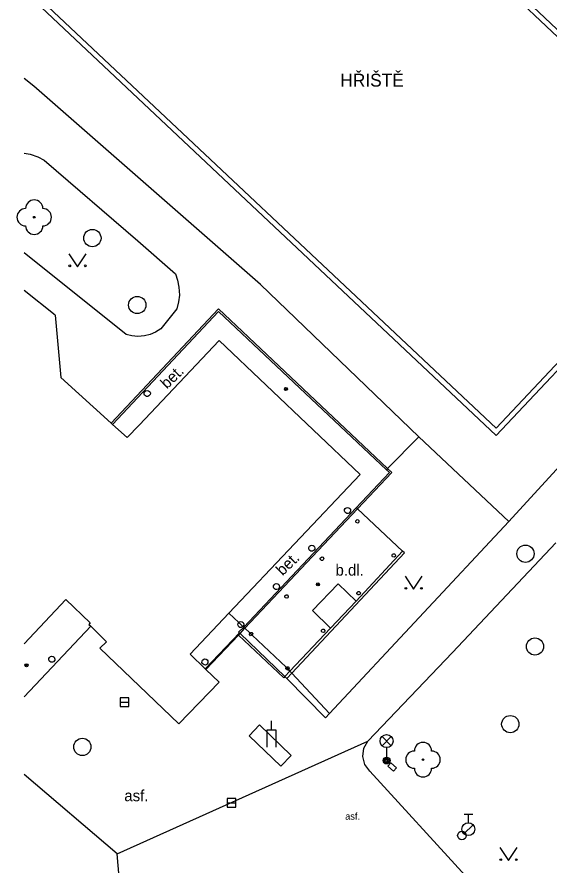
# Model space of a CAD drawing. Extents: x -598932 to -598196, y -1162207 to -1161504.
# Drawn here: x -598932.43 to -598901.6, y -1161841.73 to -1161792.56 of the extents above; entities that cross this region are included whole.
import ezdxf

# ---------------------------------------------------------------- set-up
doc = ezdxf.new("R2010")
doc.units = 0
for name, color, linetype in [('Level 22', 7, 'Continuous'), ('Level 27', 7, 'Continuous'), ('Level 28', 7, 'Continuous'), ('Level 33', 7, 'Continuous'), ('Level 36', 7, 'Continuous'), ('Level 38', 7, 'Continuous'), ('Level 39', 7, 'Continuous'), ('silnoproud - povrch.  znaky a  RIS  skut. velikost', 7, 'Continuous'), ('specificka linie pasportu komunikaci', 7, 'Continuous'), ('TM - budovy zdene_ betonove - NP', 7, 'Continuous'), ('TM - budovy zdene_ betonove - VP', 7, 'Continuous'), ('TM - chodniky - VP', 7, 'Continuous'), ('TM - plot dreveny_ kovovy - VP', 7, 'Continuous'), ('TM - pomocna konstrukcna linie', 7, 'Continuous'), ('TM - popis objektu', 7, 'Continuous'), ('TM - popis povrchu', 7, 'Continuous'), ('TM - rozhrani ploch obecne - NP', 7, 'Continuous'), ('TM - rozhrani ploch obecne - VP', 7, 'Continuous'), ('TM - vjezd na pozemek', 7, 'Continuous')]:
    doc.layers.add(name, color=color, linetype=linetype)

msp = doc.modelspace()

# ---------------------------------------------------------------- linework, layer by layer
at = {"layer": 'Level 22'}
for centre in [(-598931.43, -1161804.17), (-598908.9, -1161835.62)]:
    msp.add_circle(centre, 0.05, dxfattribs=at)
for centre, start, end in [((-598931.43, -1161803.67), 0, 180), ((-598931.93, -1161804.17), 90, 270), ((-598930.93, -1161804.17), 270, 90), ((-598931.43, -1161804.67), 180, 0), ((-598908.9, -1161835.12), 0, 180), ((-598909.4, -1161835.62), 90, 270), ((-598908.4, -1161835.62), 270, 90), ((-598908.9, -1161836.12), 180, 0)]:
    msp.add_arc(centre, 0.5, start, end, dxfattribs=at)
at = {"layer": 'Level 27'}
for p, q in [((-598926.44, -1161832.29), (-598925.94, -1161832.29)), ((-598920.24, -1161838.12), (-598919.74, -1161838.12))]:
    msp.add_line(p, q, dxfattribs=at)
for points in [[(-598926.44, -1161832.54), (-598925.94, -1161832.54), (-598925.94, -1161832.04), (-598926.44, -1161832.04)], [(-598920.24, -1161838.37), (-598919.74, -1161838.37), (-598919.74, -1161837.87), (-598920.24, -1161837.87)]]:
    msp.add_lwpolyline(points, close=True, dxfattribs=at)
for centre in [(-598928.06, -1161805.38), (-598925.46, -1161809.26), (-598902.96, -1161823.68), (-598902.41, -1161829.06), (-598903.84, -1161833.56), (-598928.64, -1161834.88)]:
    msp.add_circle(centre, 0.5, dxfattribs=at)
at = {"layer": 'Level 28'}
for p, q in [((-598906.52, -1161838.775), (-598906.02, -1161838.775)), ((-598906.27, -1161839.275), (-598906.27, -1161838.775)), ((-598906.528, -1161839.922), (-598905.998, -1161839.392))]:
    msp.add_line(p, q, dxfattribs=at)
for centre, radius in [((-598906.27, -1161839.65), 0.375), ((-598906.64, -1161840.02), 0.25)]:
    msp.add_circle(centre, radius, dxfattribs=at)
at = {"layer": 'Level 33'}
for p, q in [((-598911.275, -1161834.81), (-598910.745, -1161834.28)), ((-598911.275, -1161834.28), (-598910.745, -1161834.81)), ((-598911.01, -1161834.92), (-598911.01, -1161835.67))]:
    msp.add_line(p, q, dxfattribs=at)
for centre, radius in [((-598911.01, -1161834.545), 0.375), ((-598911.01, -1161835.67), 0.2), ((-598911.01, -1161835.67), 0.145), ((-598911.01, -1161835.67), 0.0876)]:
    msp.add_circle(centre, radius, dxfattribs=at)
at = {"layer": 'Level 36'}
for points in [[(-598929.42, -1161806.29), (-598928.92, -1161807.04), (-598928.42, -1161806.29)], [(-598909.94, -1161824.99), (-598909.44, -1161825.74), (-598908.94, -1161824.99)], [(-598904.44, -1161840.72), (-598903.94, -1161841.47), (-598903.44, -1161840.72)]]:
    msp.add_lwpolyline(points, dxfattribs=at)
for centre in [(-598929.37, -1161806.99), (-598928.471, -1161806.99), (-598909.89, -1161825.69), (-598908.991, -1161825.69), (-598904.39, -1161841.42), (-598903.491, -1161841.42)]:
    msp.add_circle(centre, 0.05, dxfattribs=at)
at = {"layer": 'Level 38'}
msp.add_line((-598917.68, -1161833.9), (-598917.68, -1161833.37), dxfattribs=at)
msp.add_lwpolyline([(-598917.93, -1161834.9), (-598917.93, -1161833.9), (-598917.43, -1161833.9), (-598917.43, -1161834.9)], dxfattribs=at)
at = {"layer": 'Level 39'}
for centre, radius in [((-598916.84, -1161814.13), 0.09), ((-598916.84, -1161814.13), 0.0398), ((-598914.99, -1161825.46), 0.09), ((-598914.99, -1161825.46), 0.0398), ((-598931.88, -1161830.15), 0.09), ((-598931.88, -1161830.15), 0.0398)]:
    msp.add_circle(centre, radius, dxfattribs=at)
at = {"layer": 'silnoproud - povrch.  znaky a  RIS  skut. velikost'}
for points in [[(-598910.76, -1161835.81), (-598910.93, -1161836)], [(-598910.93, -1161836), (-598910.61, -1161836.29)], [(-598910.44, -1161836.1), (-598910.76, -1161835.81)], [(-598910.61, -1161836.29), (-598910.44, -1161836.1)]]:
    msp.add_lwpolyline(points, dxfattribs=at)
at = {"layer": 'specificka linie pasportu komunikaci'}
msp.add_lwpolyline([(-598926.62, -1161841.08), (-598912.1, -1161834.54)], dxfattribs=at)
at = {"layer": 'TM - budovy zdene_ betonove - NP'}
for points in [[(-598925.35, -1161816.22), (-598920.71, -1161811.31)], [(-598920.71, -1161811.31), (-598912.55, -1161819.08)], [(-598925.05, -1161814.34), (-598925.01, -1161814.28)], [(-598925.05, -1161814.42), (-598925.05, -1161814.34)], [(-598925.01, -1161814.28), (-598924.96, -1161814.23)], [(-598924.96, -1161814.23), (-598924.89, -1161814.21)], [(-598924.89, -1161814.21), (-598924.81, -1161814.23)], [(-598924.81, -1161814.23), (-598924.75, -1161814.27)], [(-598924.75, -1161814.27), (-598924.72, -1161814.32)], [(-598924.72, -1161814.32), (-598924.7, -1161814.38)], [(-598924.7, -1161814.38), (-598924.71, -1161814.44)], [(-598925.03, -1161814.48), (-598925.05, -1161814.42)], [(-598924.99, -1161814.52), (-598925.03, -1161814.48)], [(-598924.93, -1161814.56), (-598924.99, -1161814.52)], [(-598924.85, -1161814.56), (-598924.93, -1161814.56)], [(-598924.78, -1161814.53), (-598924.85, -1161814.56)], [(-598924.71, -1161814.44), (-598924.78, -1161814.53)], [(-598926.97, -1161816.11), (-598926.9, -1161816.18)], [(-598926.9, -1161816.18), (-598926.04, -1161816.95)], [(-598926.04, -1161816.95), (-598925.35, -1161816.22)], [(-598912.55, -1161819.08), (-598920.15, -1161827.12)], [(-598919.22, -1161828), (-598912.69, -1161821.07)], [(-598913.44, -1161821.12), (-598913.41, -1161821.06)], [(-598913.44, -1161821.2), (-598913.44, -1161821.12)], [(-598913.42, -1161821.26), (-598913.44, -1161821.2)], [(-598913.38, -1161821.3), (-598913.42, -1161821.26)], [(-598913.41, -1161821.06), (-598913.35, -1161821.01)], [(-598913.35, -1161821.01), (-598913.28, -1161821)], [(-598913.28, -1161821), (-598913.2, -1161821.01)], [(-598913.2, -1161821.01), (-598913.14, -1161821.05)], [(-598913.14, -1161821.05), (-598913.11, -1161821.1)], [(-598913.1, -1161821.22), (-598913.14, -1161821.28)], [(-598913.11, -1161821.1), (-598913.1, -1161821.16)], [(-598913.1, -1161821.16), (-598913.1, -1161821.22)], [(-598913.32, -1161821.34), (-598913.38, -1161821.3)], [(-598913.24, -1161821.35), (-598913.32, -1161821.34)], [(-598913.17, -1161821.32), (-598913.24, -1161821.35)], [(-598913.14, -1161821.28), (-598913.17, -1161821.32)], [(-598912.8, -1161821.77), (-598912.76, -1161821.73)], [(-598912.76, -1161821.73), (-598912.72, -1161821.7)], [(-598912.72, -1161821.7), (-598912.66, -1161821.71)], [(-598912.66, -1161821.71), (-598912.61, -1161821.761)], [(-598912.8, -1161821.83), (-598912.8, -1161821.77)], [(-598912.77, -1161821.87), (-598912.8, -1161821.83)], [(-598912.68, -1161821.9), (-598912.77, -1161821.87)], [(-598912.622, -1161821.854), (-598912.68, -1161821.9)], [(-598912.61, -1161821.761), (-598912.622, -1161821.854)], [(-598915.47, -1161823.25), (-598915.42, -1161823.2)], [(-598915.42, -1161823.2), (-598915.35, -1161823.19)], [(-598915.35, -1161823.19), (-598915.27, -1161823.2)], [(-598915.27, -1161823.2), (-598915.21, -1161823.24)], [(-598915.51, -1161823.31), (-598915.47, -1161823.25)], [(-598915.51, -1161823.39), (-598915.51, -1161823.31)], [(-598915.49, -1161823.45), (-598915.51, -1161823.39)], [(-598915.45, -1161823.49), (-598915.49, -1161823.45)], [(-598915.39, -1161823.53), (-598915.45, -1161823.49)], [(-598915.31, -1161823.53), (-598915.39, -1161823.53)], [(-598915.24, -1161823.5), (-598915.31, -1161823.53)], [(-598915.2, -1161823.47), (-598915.24, -1161823.5)], [(-598915.21, -1161823.24), (-598915.18, -1161823.29)], [(-598915.17, -1161823.41), (-598915.2, -1161823.47)], [(-598915.18, -1161823.29), (-598915.16, -1161823.35)], [(-598915.16, -1161823.35), (-598915.17, -1161823.41)], [(-598910.694, -1161823.751), (-598910.66, -1161823.71)], [(-598910.66, -1161823.71), (-598910.61, -1161823.69)], [(-598910.61, -1161823.69), (-598910.55, -1161823.69)], [(-598910.55, -1161823.69), (-598910.51, -1161823.72)], [(-598910.51, -1161823.72), (-598910.49, -1161823.77)], [(-598914.85, -1161823.94), (-598914.77, -1161823.87)], [(-598914.85, -1161824), (-598914.85, -1161823.94)], [(-598914.78, -1161824.07), (-598914.85, -1161824)], [(-598914.73, -1161824.07), (-598914.78, -1161824.07)], [(-598914.77, -1161823.87), (-598914.71, -1161823.88)], [(-598914.68, -1161824.04), (-598914.73, -1161824.07)], [(-598914.71, -1161823.88), (-598914.65, -1161823.95)], [(-598914.65, -1161823.95), (-598914.68, -1161824.04)], [(-598910.694, -1161823.81), (-598910.694, -1161823.751)], [(-598910.66, -1161823.86), (-598910.694, -1161823.81)], [(-598910.57, -1161823.88), (-598910.66, -1161823.86)], [(-598910.514, -1161823.847), (-598910.57, -1161823.88)], [(-598910.49, -1161823.77), (-598910.514, -1161823.847)], [(-598917.57, -1161825.62), (-598917.56, -1161825.54)], [(-598917.54, -1161825.68), (-598917.57, -1161825.62)], [(-598917.56, -1161825.54), (-598917.53, -1161825.48)], [(-598917.5, -1161825.72), (-598917.54, -1161825.68)], [(-598917.53, -1161825.48), (-598917.47, -1161825.43)], [(-598917.47, -1161825.43), (-598917.4, -1161825.41)], [(-598917.4, -1161825.41), (-598917.32, -1161825.43)], [(-598917.32, -1161825.43), (-598917.26, -1161825.47)], [(-598917.22, -1161825.64), (-598917.29, -1161825.73)], [(-598917.26, -1161825.47), (-598917.23, -1161825.52)], [(-598917.23, -1161825.52), (-598917.22, -1161825.58)], [(-598917.22, -1161825.58), (-598917.22, -1161825.64)], [(-598913.82, -1161825.42), (-598915.3, -1161826.98)], [(-598912.78, -1161826.43), (-598913.82, -1161825.42)], [(-598917.44, -1161825.75), (-598917.5, -1161825.72)], [(-598917.37, -1161825.76), (-598917.44, -1161825.75)], [(-598917.29, -1161825.73), (-598917.37, -1161825.76)], [(-598916.9, -1161826.13), (-598916.82, -1161826.06)], [(-598916.9, -1161826.19), (-598916.9, -1161826.13)], [(-598916.82, -1161826.06), (-598916.77, -1161826.07)], [(-598916.77, -1161826.07), (-598916.71, -1161826.14)], [(-598916.71, -1161826.14), (-598916.71, -1161826.19)], [(-598912.73, -1161825.94), (-598912.65, -1161825.87)], [(-598912.73, -1161826), (-598912.73, -1161825.94)], [(-598912.66, -1161826.07), (-598912.73, -1161826)], [(-598912.61, -1161826.07), (-598912.66, -1161826.07)], [(-598912.65, -1161825.87), (-598912.59, -1161825.88)], [(-598912.56, -1161826.04), (-598912.61, -1161826.07)], [(-598912.59, -1161825.88), (-598912.53, -1161825.95)], [(-598912.54, -1161826), (-598912.56, -1161826.04)], [(-598912.53, -1161825.95), (-598912.54, -1161826)], [(-598932.017, -1161828.913), (-598929.6, -1161826.34)], [(-598929.6, -1161826.34), (-598928.18, -1161827.68)], [(-598916.87, -1161826.23), (-598916.9, -1161826.19)], [(-598916.79, -1161826.26), (-598916.87, -1161826.23)], [(-598916.74, -1161826.23), (-598916.79, -1161826.26)], [(-598916.71, -1161826.19), (-598916.74, -1161826.23)], [(-598920.15, -1161827.12), (-598922.4, -1161829.51)], [(-598915.3, -1161826.98), (-598914.26, -1161827.99)], [(-598919.58, -1161827.66), (-598919.54, -1161827.62)], [(-598919.54, -1161827.62), (-598919.46, -1161827.61)], [(-598919.46, -1161827.61), (-598919.38, -1161827.62)], [(-598919.38, -1161827.62), (-598919.32, -1161827.66)], [(-598928.18, -1161827.68), (-598928.27, -1161827.78)], [(-598928.27, -1161827.78), (-598928.15, -1161827.89)], [(-598919.63, -1161827.81), (-598919.62, -1161827.73)], [(-598919.57, -1161827.91), (-598919.63, -1161827.81)], [(-598919.62, -1161827.73), (-598919.58, -1161827.66)], [(-598919.51, -1161827.95), (-598919.57, -1161827.91)], [(-598919.43, -1161827.96), (-598919.51, -1161827.95)], [(-598919.5, -1161828.31), (-598919.22, -1161828)], [(-598919.336, -1161827.893), (-598919.43, -1161827.96)], [(-598919.29, -1161827.83), (-598919.336, -1161827.893)], [(-598919.32, -1161827.66), (-598919.3, -1161827.71)], [(-598919.3, -1161827.71), (-598919.28, -1161827.77)], [(-598919.28, -1161827.77), (-598919.29, -1161827.83)], [(-598914.78, -1161828.12), (-598914.74, -1161828.08)], [(-598914.78, -1161828.18), (-598914.78, -1161828.12)], [(-598914.74, -1161828.08), (-598914.7, -1161828.05)], [(-598914.7, -1161828.05), (-598914.64, -1161828.06)], [(-598914.64, -1161828.06), (-598914.58, -1161828.13)], [(-598914.58, -1161828.13), (-598914.61, -1161828.22)], [(-598919.6, -1161828.41), (-598919.5, -1161828.31)], [(-598918.96, -1161828.37), (-598918.93, -1161828.27)], [(-598918.89, -1161828.44), (-598918.96, -1161828.37)], [(-598918.93, -1161828.27), (-598918.88, -1161828.24)], [(-598918.79, -1161828.41), (-598918.89, -1161828.44)], [(-598918.88, -1161828.24), (-598918.82, -1161828.25)], [(-598918.82, -1161828.25), (-598918.76, -1161828.32)], [(-598918.76, -1161828.32), (-598918.79, -1161828.41)], [(-598914.75, -1161828.22), (-598914.78, -1161828.18)], [(-598914.66, -1161828.25), (-598914.75, -1161828.22)], [(-598914.61, -1161828.22), (-598914.66, -1161828.25)], [(-598930.49, -1161829.64), (-598930.42, -1161829.62)], [(-598930.42, -1161829.62), (-598930.34, -1161829.64)], [(-598922.4, -1161829.51), (-598921.524, -1161830.347)], [(-598930.58, -1161829.75), (-598930.54, -1161829.69)], [(-598930.58, -1161829.83), (-598930.58, -1161829.75)], [(-598930.56, -1161829.89), (-598930.58, -1161829.83)], [(-598930.52, -1161829.93), (-598930.56, -1161829.89)], [(-598930.54, -1161829.69), (-598930.49, -1161829.64)], [(-598930.46, -1161829.97), (-598930.52, -1161829.93)], [(-598930.38, -1161829.97), (-598930.46, -1161829.97)], [(-598930.31, -1161829.94), (-598930.38, -1161829.97)], [(-598930.34, -1161829.64), (-598930.28, -1161829.68)], [(-598930.24, -1161829.85), (-598930.31, -1161829.94)], [(-598930.28, -1161829.68), (-598930.25, -1161829.73)], [(-598930.25, -1161829.73), (-598930.24, -1161829.79)], [(-598930.24, -1161829.79), (-598930.24, -1161829.85)], [(-598921.71, -1161829.99), (-598921.7, -1161829.91)], [(-598921.68, -1161830.05), (-598921.71, -1161829.99)], [(-598921.7, -1161829.91), (-598921.67, -1161829.85)], [(-598921.64, -1161830.09), (-598921.68, -1161830.05)], [(-598921.67, -1161829.85), (-598921.61, -1161829.8)], [(-598921.58, -1161830.13), (-598921.64, -1161830.09)], [(-598921.61, -1161829.8), (-598921.54, -1161829.78)], [(-598921.54, -1161829.78), (-598921.46, -1161829.8)], [(-598921.43, -1161830.11), (-598921.51, -1161830.14)], [(-598921.46, -1161829.8), (-598921.4, -1161829.84)], [(-598921.4, -1161830.07), (-598921.43, -1161830.11)], [(-598921.4, -1161829.84), (-598921.37, -1161829.89)], [(-598921.36, -1161830.01), (-598921.4, -1161830.07)], [(-598921.37, -1161829.89), (-598921.36, -1161829.95)], [(-598921.36, -1161829.95), (-598921.36, -1161830.01)], [(-598921.51, -1161830.14), (-598921.58, -1161830.13)], [(-598921.524, -1161830.347), (-598921.48, -1161830.4)], [(-598916.85, -1161830.3), (-598916.82, -1161830.26)], [(-598916.85, -1161830.36), (-598916.85, -1161830.3)], [(-598916.78, -1161830.42), (-598916.85, -1161830.36)], [(-598916.82, -1161830.26), (-598916.77, -1161830.23)], [(-598916.73, -1161830.43), (-598916.78, -1161830.42)], [(-598916.77, -1161830.23), (-598916.71, -1161830.24)], [(-598916.68, -1161830.4), (-598916.73, -1161830.43)], [(-598916.71, -1161830.24), (-598916.65, -1161830.31)], [(-598916.65, -1161830.31), (-598916.68, -1161830.4)]]:
    msp.add_lwpolyline(points, dxfattribs=at)
at = {"layer": 'TM - budovy zdene_ betonove - VP'}
for points in [[(-598930.22, -1161809.85), (-598932.017, -1161808.424)], [(-598930.22, -1161809.85), (-598929.88, -1161813.46)], [(-598926.97, -1161816.11), (-598920.75, -1161809.49)], [(-598920.75, -1161809.49), (-598910.95, -1161818.74)], [(-598929.88, -1161813.46), (-598926.97, -1161816.11)], [(-598910.95, -1161818.74), (-598910.71, -1161818.97)], [(-598910.71, -1161818.97), (-598912.69, -1161821.07)], [(-598910.08, -1161823.54), (-598912.69, -1161821.07)], [(-598910.08, -1161823.54), (-598912.78, -1161826.43)], [(-598912.78, -1161826.43), (-598914.26, -1161827.99)], [(-598928.15, -1161827.89), (-598932.017, -1161831.97)], [(-598927.68, -1161828.35), (-598928.15, -1161827.89)], [(-598914.26, -1161827.99), (-598916.61, -1161830.48)], [(-598927.24, -1161828.78), (-598927.68, -1161828.35)], [(-598919.6, -1161828.41), (-598921.48, -1161830.4)], [(-598916.97, -1161830.87), (-598919.6, -1161828.41)], [(-598927.62, -1161829.16), (-598927.24, -1161828.78)], [(-598923.04, -1161833.54), (-598927.62, -1161829.16)], [(-598921.48, -1161830.4), (-598920.72, -1161831.12)], [(-598916.61, -1161830.48), (-598916.9, -1161830.8)], [(-598916.9, -1161830.8), (-598916.97, -1161830.87)], [(-598920.72, -1161831.12), (-598923.04, -1161833.54)]]:
    msp.add_lwpolyline(points, dxfattribs=at)
at = {"layer": 'TM - chodniky - VP'}
for points in [[(-598909.14, -1161816.9), (-598918.32, -1161808.07), (-598931.46, -1161796.58), (-598932.017, -1161796.135)], [(-598932.017, -1161800.452), (-598931.67, -1161800.51)], [(-598931.67, -1161800.51), (-598931.23, -1161800.66), (-598930.86, -1161800.87), (-598925.42, -1161805.54), (-598923.25, -1161807.45)], [(-598926.11, -1161810.97), (-598932.017, -1161806.242)], [(-598923.25, -1161807.45), (-598923.12, -1161807.82), (-598923.04, -1161808.22), (-598923.02, -1161808.69), (-598923.06, -1161809.07), (-598923.17, -1161809.48), (-598924.1, -1161810.64)], [(-598924.1, -1161810.64), (-598924.41, -1161810.83), (-598924.71, -1161810.97), (-598925.03, -1161811.05), (-598925.43, -1161811.09), (-598925.78, -1161811.05), (-598926.11, -1161810.97)], [(-598909.14, -1161816.9), (-598910.95, -1161818.74)], [(-598907.19, -1161829.41), (-598901.21, -1161823.05)], [(-598912.1, -1161834.54), (-598907.19, -1161829.41)], [(-598911.98, -1161836.28), (-598912.27, -1161835.9), (-598912.39, -1161835.44), (-598912.33, -1161834.96), (-598912.1, -1161834.54)], [(-598899.36, -1161850.06), (-598906.43, -1161842.36), (-598911.98, -1161836.28)], [(-598926.24, -1161845.61), (-598926.62, -1161841.08)]]:
    msp.add_lwpolyline(points, dxfattribs=at)
at = {"layer": 'TM - plot dreveny_ kovovy - VP'}
for points in [[(-598891.67, -1161802.61), (-598918.56, -1161777.23)], [(-598931.61, -1161791.02), (-598904.66, -1161816.41)], [(-598904.66, -1161816.41), (-598891.67, -1161802.61)], [(-598900.54, -1161818.13), (-598903.93, -1161821.82)], [(-598903.93, -1161821.82), (-598914.32, -1161832.94), (-598916.5, -1161830.6)], [(-598919.58, -1161827.66), (-598920.15, -1161827.12)], [(-598919.45, -1161827.78), (-598919.58, -1161827.66)], [(-598919.336, -1161827.893), (-598919.45, -1161827.78)], [(-598919.29, -1161827.93), (-598919.336, -1161827.893)], [(-598919.22, -1161828), (-598919.29, -1161827.93)], [(-598918.93, -1161828.27), (-598919.22, -1161828)], [(-598918.86, -1161828.34), (-598918.93, -1161828.27)], [(-598916.61, -1161830.48), (-598916.68, -1161830.4), (-598916.75, -1161830.33)], [(-598916.5, -1161830.6), (-598916.61, -1161830.48)]]:
    msp.add_lwpolyline(points, dxfattribs=at)
at = {"layer": 'TM - pomocna konstrukcna linie'}
msp.add_lwpolyline([(-598926.62, -1161841.08), (-598932.017, -1161836.471)], dxfattribs=at)
at = {"layer": 'TM - rozhrani ploch obecne - NP'}
for points in [[(-598926.9, -1161816.18), (-598920.75, -1161809.63), (-598911.02, -1161818.81)], [(-598910.95, -1161818.74), (-598911.02, -1161818.81)], [(-598911.02, -1161818.81), (-598910.85, -1161818.97), (-598912.77, -1161821.01)], [(-598912.77, -1161821.01), (-598919.29, -1161827.93)], [(-598912.69, -1161821.07), (-598912.77, -1161821.01)], [(-598919.29, -1161827.93), (-598919.584, -1161828.222), (-598919.54, -1161828.274)], [(-598919.54, -1161828.274), (-598921.524, -1161830.347)], [(-598919.54, -1161828.274), (-598919.5, -1161828.31)], [(-598919.5, -1161828.31), (-598916.9, -1161830.8)]]:
    msp.add_lwpolyline(points, dxfattribs=at)
at = {"layer": 'TM - rozhrani ploch obecne - VP'}
for points in [[(-598918.57, -1161776.8), (-598891.25, -1161802.6)], [(-598904.65, -1161816.83), (-598932.017, -1161791.043)], [(-598891.25, -1161802.6), (-598904.65, -1161816.83)], [(-598903.93, -1161821.82), (-598909.14, -1161816.9)], [(-598916.5, -1161830.6), (-598909.98, -1161823.63), (-598910.08, -1161823.54)], [(-598916.79, -1161830.91), (-598916.5, -1161830.6)], [(-598916.9, -1161830.8), (-598916.79, -1161830.91)], [(-598916.79, -1161830.91), (-598914.55, -1161833.19)], [(-598914.55, -1161833.19), (-598914.32, -1161832.94)], [(-598918.98, -1161834.24), (-598918.38, -1161833.61), (-598916.53, -1161835.38), (-598917.13, -1161836), (-598918.98, -1161834.24)]]:
    msp.add_lwpolyline(points, dxfattribs=at)
at = {"layer": 'TM - vjezd na pozemek'}
for points in [[(-598918.86, -1161828.34), (-598918.79, -1161828.41), (-598916.82, -1161830.26)], [(-598916.82, -1161830.26), (-598916.75, -1161830.33)]]:
    msp.add_lwpolyline(points, dxfattribs=at)

# ---------------------------------------------------------------- texts
at = {"layer": 'TM - popis objektu'}
msp.add_text('HŘIŠTĚ', height=0.75, dxfattribs=at).set_placement((-598913.69, -1161796.6))
at = {"layer": 'TM - popis povrchu'}
for p in [(-598923.74, -1161814.16), (-598917.04, -1161824.99)]:
    msp.add_text('bet.', height=0.65, rotation=44.04, dxfattribs=at).set_placement(p)
for s, height, p in [('b.dl.', 0.65, (-598913.97, -1161824.95)), ('asf.', 0.65, (-598926.21, -1161838.03)), ('asf.', 0.4, (-598913.41, -1161839.1))]:
    msp.add_text(s, height=height, dxfattribs=at).set_placement(p)

doc.saveas('drawing.dxf')
